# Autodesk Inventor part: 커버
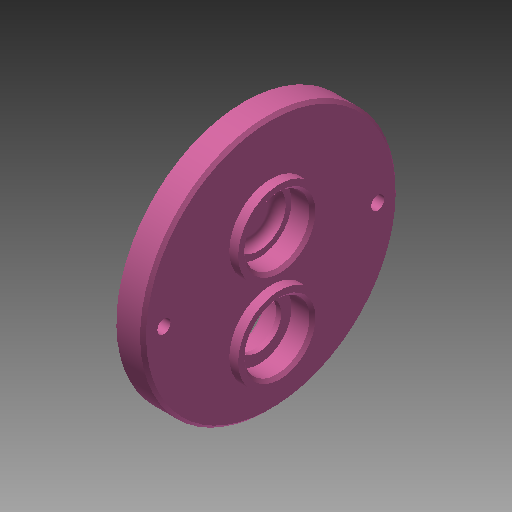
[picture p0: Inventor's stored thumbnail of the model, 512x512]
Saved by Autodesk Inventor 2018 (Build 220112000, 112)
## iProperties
Created: 2016-02
Part Number: 커버
Material: 알루미늄 6061
Document SubType Name: Modeling
Designer: mduedu
Density: 2.71 g/cm^3
Appearance: 분홍색
Author: mduedu
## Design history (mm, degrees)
sketch "스케치1"
  geometry: C1 r 43 at (0, 0); 1 further point
  constraints: 1 centre point, 1 coincident
  dimensions: "d0" = 86 diameter of C1
extrude "돌출1" new body sketch "스케치1" distance "d1" = 9; taper "d2" = 0 deg
sketch "스케치2"
  geometry: C1 r 14 at (0, 11); 1 further point
  constraints: 1 centre point, 1 vertical alignment
  dimensions: "d3" = 28 diameter of C1; "d6" = 11 distance of C1.centre point (0, 0)
extrude "돌출2" join sketch "스케치2" distance "d7" = 3; taper "d8" = 0 deg
sketch "스케치3"
  geometry: C1 r 14 at (0, -20); 1 further point
  constraints: 1 centre point, 1 vertical alignment
  dimensions: "d9" = 28 diameter of C1; "d10" = 20 distance of C1.centre point (0, 0)
extrude "돌출3" join sketch "스케치3" distance "d11" = 3; taper "d12" = 0 deg
hole "구멍1" diameter "d15" = 22; stored, may be unused: countersink angle "d19" = 90 deg, drill point angle "d21" = 0 deg; dims "d13" = 10, "d14" = 10, "d16" = 6, "d17" = 4, "d18" = 2, "d20" = 7
hole "구멍2" diameter "d24" = 18; stored, may be unused: countersink angle "d28" = 90 deg, drill point angle "d30" = 0 deg; dims "d25" = 6, "d26" = 4, "d27" = 2, "d29" = 3, "d95" = 10, "d96" = 10
fillet "모깎기7" dims "d97" = 3
hole "구멍3" diameter "d33" = 22; stored, may be unused: countersink angle "d37" = 90 deg, drill point angle "d39" = 0 deg; dims "d34" = 6, "d35" = 4, "d36" = 2, "d38" = 7, "d73" = 10, "d74" = 10
sketch "스케치4"
  geometry: C1 r 14 at (0, -20) reference; C2 r 18 at (0, -20); 1 further point
  constraints: 1 centre point, 1 coincident
  dimensions: "d40" = 36 diameter of C2
extrude "돌출4" join sketch "스케치4" distance "d41" = 4; taper "d42" = 0 deg
hole "구멍4" diameter "d45" = 22; stored, may be unused: countersink angle "d49" = 90 deg, drill point angle "d51" = 0 deg; dims "d46" = 6, "d47" = 4, "d48" = 2, "d50" = 7.3, "d98" = 10, "d99" = 10
hole "구멍5" diameter "d54" = 15; stored, may be unused: countersink angle "d58" = 90 deg, drill point angle "d60" = 0 deg; dims "d52" = 10, "d53" = 10, "d55" = 6, "d56" = 4, "d57" = 2, "d59" = 7
chamfer "모따기1" distance "d63" = 1; stored, may be unused: second distance "d64" = 2, angle "d65" = 45 deg
chamfer "모따기3" distance "d100" = 0.7; stored, may be unused: second distance "d101" = 2, angle "d102" = 30 deg
sketch "스케치5" dims "d67" = 72
  geometry: 4 further points
  constraints: 2 horizontal alignment, 1 coincident, 5 other
  dimensions: "d71" = 360 deg dimension on point (0, 0) point (-36, 0) (derived)
sketch "스케치6"
  geometry: 2 further points
hole "구멍6" sketch "스케치6" at (-36, 0), (36, 0) diameter "d76" = 4.5; stored, may be unused: countersink angle "d80" = 90 deg, drill point angle "d82" = 0 deg; dims "d77" = 6, "d78" = 8, "d79" = 4.6, "d81" = 8
chamfer "모따기2" distance "d90" = 1; stored, may be unused: second distance "d91" = 2, angle "d92" = 45 deg
node "솔리드1"
